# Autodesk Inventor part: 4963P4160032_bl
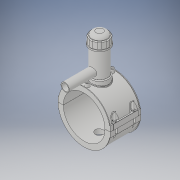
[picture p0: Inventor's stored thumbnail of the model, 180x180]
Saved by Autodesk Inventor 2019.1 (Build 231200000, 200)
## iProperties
Created: 2017-07
Part Number: 4963P4160032_bl
Material: Generic
Document SubType Name: Modeling
Designer: KIM
Density: 1 g/cm^3
Appearance: Default
Author: KIM
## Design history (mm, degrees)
derived "4963P4.ipt"
feature "Solid1::4963P4.ipt" dims "ScaleForDerivedMember" = 10
feature "Solid2::4963P4.ipt" dims "ScaleForDerivedMember" = 10
feature "Solid3::4963P4.ipt" dims "ScaleForDerivedMember" = 10
tag "TaggingFeature1"
body "Solid1"
body "Solid2"
body "Solid3"
other parameters: "B_" = 199 [user parameter], "L_" = 118 [user parameter], "d_t" = 6 [user parameter], "H_2" = 177 [user parameter], "H_1" = 56 [user parameter], "d_1" = 32 [user parameter], "H_" = 132 [user parameter], "d1" = 195.2 [user parameter], "d148" = 2.4 [user parameter], "d160" = 2.4 [user parameter], "d169" = 3.75 [user parameter], "d192" = 8 [user parameter], "d2" = 199 [user parameter], "d4" = 118 [user parameter], "d5" = 0 [user parameter], "d6" = 0.1 [user parameter], "d8" = 0 [user parameter], "d19" = 6 [user parameter], "d20" = 6 [user parameter], "d21" = 70.8 [user parameter], "d23" = 0 [user parameter], "d24" = 35.4 [user parameter], "d26" = 0 [user parameter], "d27" = 3 [user parameter], "d28" = 3 [user parameter], "d29" = 3 [user parameter], "d30" = 53.33333 [user parameter], "d31" = 6 [user parameter], "d32" = 0 [user parameter], "d33" = 0 [user parameter], "d34" = 0.6 [user parameter], "d40" = 101.504 [user parameter], "d41" = 72 [user parameter], "d43" = 0 [user parameter], "d45" = 0 [user parameter], "d47" = 168.4 [user parameter], "d70" = 15 [user parameter], "d72" = 0 [user parameter], "d73" = 6 [user parameter], "d75" = 5 [user parameter], "d76" = 0 [user parameter], "d77" = 8 [user parameter], "d79" = 15 [user parameter], "d80" = 47.2 [user parameter], "d82" = 5 deg [user parameter], "d84" = 4 [user parameter], "d85" = 14 [user parameter], "d86" = 0 [user parameter], "d87" = 3 [user parameter], "d88" = 0 [user parameter], "d89" = 1 [user parameter], "d90" = 1 [user parameter], "d91" = 94.4 [user parameter], "d92" = 0 [user parameter], "d93" = 0.5 [user parameter], "d94" = 84.21053 [user parameter], "d96" = 199.104 [user parameter], "d97" = 2.36 [user parameter], "d98" = 0 [user parameter], "d102" = 1.6 [user parameter], "d120" = 140 deg [user parameter], "d121" = 24.228 [user parameter], "d122" = 20 deg [user parameter], "d123" = 390.4 [user parameter], "d124" = 117.12 [user parameter], "d126" = 0 [user parameter], "d143" = 164.8 [user parameter], "d145" = 27.07692 [user parameter], "d149" = 2.4 [user parameter], "d150" = 29.78462 [user parameter], "d153" = 118 [user parameter], "d154" = 0 [user parameter], "d156" = 97.6 [user parameter], "d157" = 160 deg [user parameter], "d159" = 7.04 [user parameter], "d161" = 2.4 [user parameter], "d162" = 70.8 [user parameter], "d163" = 0 [user parameter], "d167" = 16 [user parameter], "d168" = 95.21951 [user parameter], "d170" = 3.75 [user parameter], "d172" = 0 [user parameter], "d173" = 1 [user parameter], "d176" = 20 deg [user parameter], "d177" = 11.2 [user parameter], "d178" = 35.2 [user parameter], "d180" = 0 [user parameter], "d183" = 14.08 [user parameter], "d184" = 8.96 [user parameter], "d185" = 38.35 [user parameter], "d186" = 38.35 [user parameter], "d187" = 97.6 [user parameter], "d188" = 10.56 [user parameter], "d189" = 11.2 [user parameter], "d190" = 0 [user parameter], "d191" = 146.4 [user parameter], "d193" = 8 [user parameter], "d194" = 4.13 [user parameter], "d195" = 90 deg [user parameter], "d197" = 0 [user parameter], "d199" = 0 [user parameter], "d200" = 17.6 [user parameter], "d202" = 0 [user parameter], "d203" = 177 [user parameter], "d204" = 68.4 [user parameter], "d205" = 50.4 [user parameter], "d206" = 61.2 [user parameter], "d207" = 132.75 [user parameter], "d208" = 138.06 [user parameter], "d209" = 164.61 [user parameter], "d210" = 61.92 [user parameter], "d211" = 72 [user parameter], "d212" = 57.6 [user parameter], "d213" = 36 [user parameter], "d216" = 0 [user parameter], "d217" = 16 [user parameter], "d218" = 16 [user parameter], "d219" = 3.2 [user parameter], "d224" = 0 [user parameter], "d225" = 56 [user parameter]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
